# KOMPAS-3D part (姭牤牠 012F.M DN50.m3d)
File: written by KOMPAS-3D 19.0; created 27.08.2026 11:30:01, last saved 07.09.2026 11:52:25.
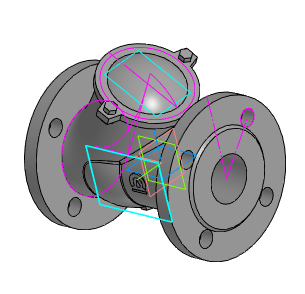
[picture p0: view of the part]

Document properties: Автор: Энергия; Полное имя файла: Z:\3.Личные\kachalov\001_3d для проектировщиков\х.х Тип 012F\012F.M\Клапан 012F.M DN50.m3d

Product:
- Part/product: (unnamed)  | designation Клапан 012F.M DN50
    Масса: 14.9743

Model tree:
1. Эскиз:1
2. Элемент вращения:1
     Угол 1 = 360
3. Эскиз:2  (with: Элемент вращения:1)
4. Перпендикулярная плоскость:1
5. Эскиз:3
6. Эскиз:12  (with: Элемент вращения:1)
7. Элемент по сечениям:1
8. Эскиз:7
9. Элемент выдавливания:2
     Расстояние 2 = 8
10. Эскиз:9  (with: Элемент выдавливания:2)
11. Элемент вращения:2  (with: Элемент выдавливания:2)
     Угол 1 = 360
12. Эскиз:10  (with: Элемент вращения:1)
13. Элемент выдавливания:3  (with: Элемент вращения:1)
     Расстояние 2 = 16
14. Массив по концентрической сетке:1  (with: Элемент выдавливания:3, Эскиз:10, Элемент вращения:1)  (4 pattern instances)
     Шаг 2 = 360
15. Эскиз:11  (with: Элемент вращения:1)
16. Элемент выдавливания:4  (with: Элемент вращения:1)
     Расстояние 2 = 16
17. Массив по концентрической сетке:2  (with: Элемент выдавливания:4, Эскиз:11, Элемент вращения:1)  (4 pattern instances)
     Шаг 2 = 360
18. Скругление:6  (with: Элемент выдавливания:2)
     Радиус = 3
19. Эскиз:13  (with: Элемент выдавливания:2)
20. Элемент выдавливания:5  (with: Элемент выдавливания:2)
     Расстояние 1 = 5.5; Расстояние 2 = 13.5; Смещение 2 = 5.5
21. Зеркальный массив:3
22. Экземпляр ( 1 )
23. Экземпляр ( 2 )  (with: Элемент выдавливания:5)
24. Касательная плоскость:1  (with: Элемент вращения:1)
     Угол = 90
25. Смещенная плоскость:1
     Расстояние = 1
26. Эскиз:14
27. Элемент выдавливания:6  (with: Элемент вращения:1)
     Расстояние 1 = -1.00046; Расстояние 2 = 1
28. Эскиз:15  (with: Элемент вращения:1)
29. Элемент вращения:3
     Угол 1 = 360
30. Скругление:10  (with: Элемент вращения:3, Элемент по сечениям:1)
     Радиус = 5
31. Эскиз:16
32. Элемент выдавливания:7
     Расстояние 1 = 50
33. Эскиз:17  (with: Элемент выдавливания:7)
34. Элемент выдавливания:8
     Расстояние 1 = 6.5
35. Эскиз:18  (with: Элемент вращения:1)
36. Элемент выдавливания:9

Expressions: Dn/2; D/2; D2/2; D2/2-5; 360/(2*n); 360/(n*2); D2-6; D2-5; (D2+5)/2
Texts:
  Клапан 012F.M DN50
